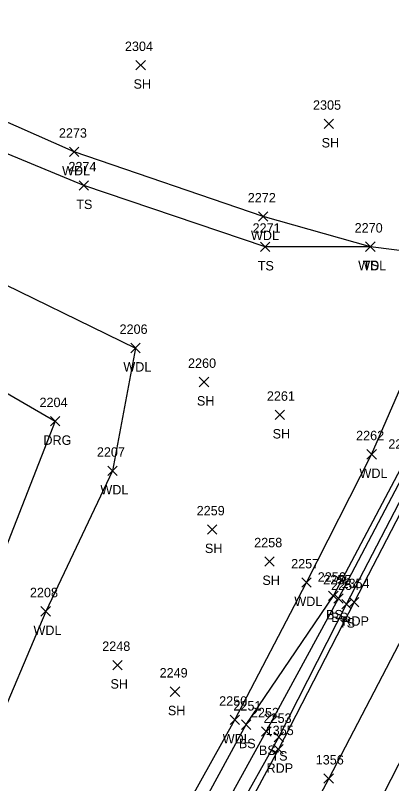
# Model space of a CAD drawing. Extents: x 1885914 to 1887218, y 756253 to 760620.
# Drawn here: x 1886566 to 1886645.8, y 760195 to 760358 of the extents above; entities that cross this region are included whole.
import ezdxf

# ---------------------------------------------------------------- set-up
doc = ezdxf.new("R2010")
doc.units = 0
for name, color, linetype in [('L_A', 7, 'Continuous'), ('L_I', 7, 'Continuous'), ('L_TIC', 7, 'Continuous'), ('LAWA', 7, 'Continuous'), ('LELB', 7, 'Continuous'), ('P_A', 7, 'Continuous'), ('P_I', 7, 'Continuous'), ('P_TIC', 7, 'Continuous'), ('PET', 7, 'Continuous'), ('PRC', 7, 'Continuous'), ('R_A', 7, 'Continuous'), ('R_I', 7, 'Continuous'), ('R_TIC', 7, 'Continuous'), ('RDG', 7, 'Continuous')]:
    doc.layers.add(name, color=color, linetype=linetype)

msp = doc.modelspace()

# ---------------------------------------------------------------- linework, layer by layer
at = {"layer": 'L_TIC'}
for points in [[(1886591.55, 760346.39), (1886593.55, 760348.39)], [(1886593.55, 760346.39), (1886591.55, 760348.39)], [(1886631.45, 760333.93), (1886633.45, 760335.93)], [(1886633.45, 760333.93), (1886631.45, 760335.93)], [(1886577.46, 760328), (1886579.46, 760330)], [(1886579.46, 760328), (1886577.46, 760330)], [(1886579.48, 760320.86), (1886581.48, 760322.86)], [(1886581.48, 760320.86), (1886579.48, 760322.86)], [(1886617.53, 760314.27), (1886619.53, 760316.27)], [(1886619.53, 760314.27), (1886617.53, 760316.27)], [(1886617.98, 760307.84), (1886619.98, 760309.84)], [(1886619.98, 760307.84), (1886617.98, 760309.84)], [(1886640.28, 760307.88), (1886642.28, 760309.88)], [(1886642.28, 760307.88), (1886640.28, 760309.88)], [(1886640.28, 760307.88), (1886642.28, 760309.88)], [(1886642.28, 760307.88), (1886640.28, 760309.88)], [(1886590.46, 760286.38), (1886592.46, 760288.38)], [(1886592.46, 760286.38), (1886590.46, 760288.38)], [(1886604.99, 760279.17), (1886606.99, 760281.17)], [(1886606.99, 760279.17), (1886604.99, 760281.17)], [(1886621.06, 760272.19), (1886623.06, 760274.19)], [(1886623.06, 760272.19), (1886621.06, 760274.19)], [(1886640.55, 760263.82), (1886642.55, 760265.82)], [(1886642.55, 760263.82), (1886640.55, 760265.82)], [(1886585.6, 760260.32), (1886587.6, 760262.32)], [(1886587.6, 760260.32), (1886585.6, 760262.32)], [(1886606.7, 760247.88), (1886608.7, 760249.88)], [(1886608.7, 760247.88), (1886606.7, 760249.88)], [(1886618.89, 760241.11), (1886620.89, 760243.11)], [(1886620.89, 760241.11), (1886618.89, 760243.11)], [(1886626.73, 760236.63), (1886628.73, 760238.63)], [(1886628.73, 760236.63), (1886626.73, 760238.63)], [(1886632.43, 760233.81), (1886634.43, 760235.81)], [(1886634.43, 760233.81), (1886632.43, 760235.81)], [(1886633.53, 760233.24), (1886635.53, 760235.24)], [(1886635.53, 760233.24), (1886633.53, 760235.24)], [(1886635.21, 760232.06), (1886637.21, 760234.06)], [(1886637.21, 760232.06), (1886635.21, 760234.06)], [(1886571.4, 760230.51), (1886573.4, 760232.51)], [(1886573.4, 760230.51), (1886571.4, 760232.51)], [(1886586.66, 760219.12), (1886588.66, 760221.12)], [(1886588.66, 760219.12), (1886586.66, 760221.12)], [(1886598.84, 760213.48), (1886600.84, 760215.48)], [(1886600.84, 760213.48), (1886598.84, 760215.48)], [(1886611.55, 760207.5), (1886613.55, 760209.5)], [(1886613.55, 760207.5), (1886611.55, 760209.5)], [(1886613.93, 760206.48), (1886615.93, 760208.48)], [(1886615.93, 760206.48), (1886613.93, 760208.48)], [(1886618.2, 760205.04), (1886620.2, 760207.04)], [(1886620.2, 760205.04), (1886618.2, 760207.04)], [(1886620.88, 760203.85), (1886622.88, 760205.85)], [(1886622.88, 760203.85), (1886620.88, 760205.85)]]:
    msp.add_lwpolyline(points, dxfattribs=at)
at = {"layer": 'LAWA'}
msp.add_lwpolyline([(1886557.49, 760303.87), (1886591.46, 760287.38), (1886586.6, 760261.32), (1886572.4, 760231.51), (1886560.84, 760204.17), (1886553.53, 760184.95), (1886554.61, 760165.79), (1886555.43, 760150.16), (1886559.73, 760135.93), (1886571.71, 760133.88), (1886584.52, 760154.18), (1886595.31, 760177.7), (1886612.55, 760208.5), (1886627.73, 760237.63), (1886641.55, 760264.82), (1886659.69, 760306.49), (1886641.28, 760308.88), (1886618.53, 760315.27), (1886578.46, 760329), (1886533.46, 760348.84), (1886508.34, 760359)], dxfattribs=at)
at = {"layer": 'LELB'}
for points in [[(1886641.28, 760308.88), (1886618.98, 760308.84), (1886580.48, 760321.86), (1886536.04, 760340.26), (1886518.52, 760341.71), (1886481, 760356.9)], [(1886566.15, 760118.03), (1886586.71, 760153.39), (1886597.76, 760175.93), (1886614.93, 760207.48), (1886633.43, 760234.81), (1886648.4, 760263.02), (1886665.33, 760301.86), (1886680.82, 760329.69), (1886690.65, 760354.87)], [(1886569.48, 760114.6), (1886588.52, 760152.37), (1886601.13, 760173.25), (1886619.2, 760206.04), (1886634.53, 760234.24), (1886649.4, 760262.46), (1886668.06, 760300.13), (1886683.15, 760328.96), (1886694.25, 760353.25)], [(1886571.83, 760112.64), (1886591.92, 760150.85), (1886603.31, 760171.7), (1886621.88, 760204.85), (1886636.21, 760233.06), (1886650.97, 760261.46), (1886669.74, 760299.13), (1886684.78, 760328.15), (1886696.37, 760352.36)]]:
    msp.add_lwpolyline(points, dxfattribs=at)
at = {"layer": 'P_TIC'}
for points in [[(1886636.84, 760232.45), (1886638.84, 760234.45)], [(1886638.84, 760232.45), (1886636.84, 760234.45)], [(1886620.76, 760201.26), (1886622.76, 760203.26)], [(1886622.76, 760201.26), (1886620.76, 760203.26)], [(1886631.44, 760195.03), (1886633.44, 760197.03)], [(1886633.44, 760195.03), (1886631.44, 760197.03)]]:
    msp.add_lwpolyline(points, dxfattribs=at)
at = {"layer": 'PET'}
for points in [[(1886697.38, 760351.34), (1886683.55, 760324.32), (1886670.92, 760299), (1886655.54, 760267.57), (1886637.84, 760233.45), (1886621.76, 760202.26), (1886604.96, 760170.92), (1886588.13, 760139.08), (1886573.73, 760111.63), (1886569.92, 760108.66), (1886558.78, 760086.23), (1886539.06, 760048.09), (1886538, 760043.12), (1886529.58, 760026.84), (1886519.95, 760007.47), (1886505.21, 759975.04), (1886485.32, 759931.76)], [(1886719.61, 760339.51), (1886705.93, 760312.96), (1886693.41, 760288.8), (1886676.56, 760255.91), (1886659.38, 760222.81), (1886642.61, 760189.88), (1886625.62, 760158.68), (1886608.91, 760127.1), (1886594.01, 760097.91), (1886581.16, 760073.4), (1886568, 760045.02), (1886556.6, 760025.44), (1886542.61, 759998.54), (1886526.14, 759964.92), (1886507.07, 759922.75)]]:
    msp.add_lwpolyline(points, dxfattribs=at)
at = {"layer": 'PRC'}
msp.add_lwpolyline([(1886708.51, 760345.16), (1886695.27, 760318.5), (1886682.3, 760293.2), (1886665.98, 760261.32), (1886649.02, 760227.78), (1886632.44, 760196.03), (1886615.49, 760164.09), (1886599.17, 760133.16), (1886583.22, 760103.13), (1886570.57, 760078.83), (1886555.85, 760051.11), (1886540.62, 760021), (1886531.87, 760002.72), (1886516.05, 759969.43), (1886496.99, 759926.69)], dxfattribs=at)
at = {"layer": 'R_TIC'}
for points in [[(1886573.43, 760270.84), (1886575.43, 760272.84)], [(1886575.43, 760270.84), (1886573.43, 760272.84)]]:
    msp.add_lwpolyline(points, dxfattribs=at)
at = {"layer": 'RDG'}
msp.add_lwpolyline([(1886545.75, 760291.46), (1886562.57, 760278.75), (1886574.43, 760271.84), (1886560.81, 760237.29), (1886547.52, 760211.75), (1886539.01, 760192.05), (1886538.13, 760179.08), (1886537.48, 760165.92), (1886548.05, 760139.99), (1886558.75, 760116.26), (1886568.3, 760110.67), (1886571.83, 760112.64), (1886573.56, 760113.12)], dxfattribs=at)

# ---------------------------------------------------------------- texts
at = {"layer": 'L_A'}
for s, p in [('SH', (1886591.04, 760342.39)), ('SH', (1886630.94, 760329.93)), ('WDL', (1886575.88, 760324)), ('TS', (1886578.89, 760316.86)), ('WDL', (1886615.95, 760310.27)), ('TS', (1886617.39, 760303.84)), ('WDL', (1886638.7, 760303.88)), ('TS', (1886639.69, 760303.88)), ('WDL', (1886588.88, 760282.38)), ('SH', (1886604.48, 760275.17)), ('SH', (1886620.55, 760268.19)), ('WDL', (1886638.97, 760259.82)), ('WDL', (1886584.01, 760256.32)), ('SH', (1886606.18, 760243.88)), ('SH', (1886618.37, 760237.11)), ('WDL', (1886625.15, 760232.63)), ('BS', (1886631.87, 760229.81)), ('BS', (1886632.97, 760229.24)), ('TS', (1886634.62, 760228.06)), ('WDL', (1886569.81, 760226.51)), ('SH', (1886586.15, 760215.12)), ('SH', (1886598.32, 760209.48)), ('WDL', (1886609.96, 760203.5)), ('BS', (1886613.37, 760202.48)), ('BS', (1886617.64, 760201.04)), ('TS', (1886620.29, 760199.85))]:
    msp.add_text(s, height=2, dxfattribs=at).set_placement(p)
at = {"layer": 'L_I'}
for s, p in [('2304', (1886589.21, 760350.39)), ('2305', (1886629.11, 760337.93)), ('2273', (1886575.2, 760332)), ('2274', (1886577.22, 760324.86)), ('2272', (1886615.27, 760318.27)), ('2271', (1886616.29, 760311.84)), ('2270', (1886637.94, 760311.88)), ('2270', (1886637.94, 760311.88)), ('2206', (1886588.07, 760290.38)), ('2260', (1886602.6, 760283.17)), ('2261', (1886619.32, 760276.19)), ('2262', (1886638.25, 760267.82)), ('2263', (1886645.09, 760266.02)), ('2207', (1886583.26, 760264.32)), ('2259', (1886604.43, 760251.88)), ('2258', (1886616.63, 760245.11)), ('2257', (1886624.47, 760240.63)), ('2256', (1886630.11, 760237.81)), ('2255', (1886631.27, 760237.24)), ('2254', (1886632.95, 760236.06)), ('2208', (1886569.06, 760234.51)), ('2248', (1886584.4, 760223.12)), ('2249', (1886596.57, 760217.48)), ('2250', (1886609.2, 760211.5)), ('2251', (1886612.23, 760210.48)), ('2252', (1886615.94, 760209.04)), ('2253', (1886618.62, 760207.85))]:
    msp.add_text(s, height=2, dxfattribs=at).set_placement(p)
at = {"layer": 'P_A'}
for p in [(1886635.33, 760228.45), (1886619.25, 760197.26)]:
    msp.add_text('RDP', height=2, dxfattribs=at).set_placement(p)
at = {"layer": 'P_I'}
for s, p in [('1354', (1886635.15, 760236.45)), ('1355', (1886619.07, 760205.26)), ('1356', (1886629.69, 760199.03))]:
    msp.add_text(s, height=2, dxfattribs=at).set_placement(p)
at = {"layer": 'R_A'}
msp.add_text('DRG', height=2, dxfattribs=at).set_placement((1886571.92, 760266.84))
at = {"layer": 'R_I'}
msp.add_text('2204', height=2, dxfattribs=at).set_placement((1886571.09, 760274.84))

doc.saveas('drawing.dxf')
